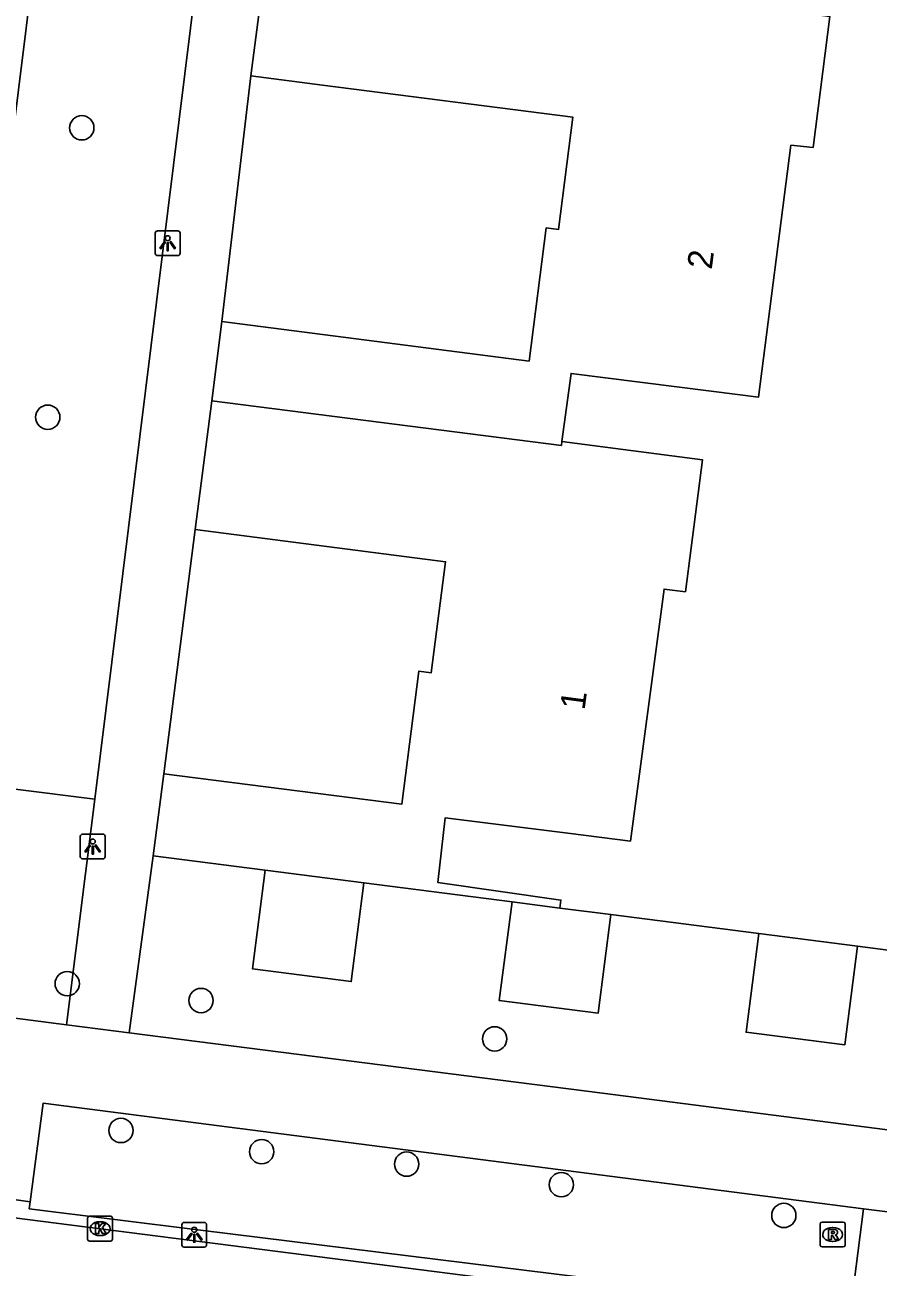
# Model space of a CAD drawing. Extents: x 162186 to 163152, y 385513 to 386513.
# Drawn here: x 162370.33 to 162404.64, y 386051 to 386100.97 of the extents above; entities that cross this region are included whole.
import ezdxf

# ---------------------------------------------------------------- set-up
doc = ezdxf.new("R2010")
doc.units = 0
for name, color, linetype in [('IMGEO_Boom', 7, 'Continuous'), ('IMGEO_Groenvoorziening', 7, 'Continuous'), ('IMGEO_Kolk', 7, 'Continuous'), ('IMGEO_Lichtpunt', 7, 'Continuous'), ('IMGEO_Muur', 7, 'Continuous'), ('IMGEO_Pand', 7, 'Continuous'), ('IMGEO_Pand_nummerreeks', 7, 'Continuous'), ('IMGEO_Rijbaan_lokaal_open', 7, 'Continuous'), ('IMGEO_Rioolput', 7, 'Continuous'), ('IMGEO_Voetpad_open', 7, 'Continuous')]:
    doc.layers.add(name, color=color, linetype=linetype)

msp = doc.modelspace()

# ---------------------------------------------------------------- linework, layer by layer
at = {"layer": 'IMGEO_Boom'}
for centre in [(162372.62, 386096.827), (162371.252, 386085.186), (162372.034, 386062.399), (162377.416, 386061.723), (162389.22, 386060.18), (162374.193, 386056.495), (162379.854, 386055.641), (162385.68, 386055.142), (162391.899, 386054.314), (162400.847, 386053.077)]:
    msp.add_circle(centre, 0.489, dxfattribs=at)
at = {"layer": 'IMGEO_Groenvoorziening'}
for points in [[(162373.204, 386123.496), (162366.618, 386070.643)], [(162366.618, 386070.643), (162373.139, 386069.824)], [(162383.966, 386066.454), (162383.456, 386062.487), (162379.488, 386062.996), (162379.998, 386066.964)], [(162393.886, 386065.179), (162393.376, 386061.212), (162389.408, 386061.722), (162389.918, 386065.69)], [(162391.837, 386065.443), (162393.886, 386065.179)], [(162393.886, 386065.179), (162399.838, 386064.413)], [(162403.805, 386063.903), (162403.294, 386059.936), (162399.328, 386060.446), (162399.838, 386064.413)], [(162399.838, 386064.413), (162403.805, 386063.903)], [(162403.805, 386063.903), (162406.781, 386063.52)]]:
    msp.add_lwpolyline(points, dxfattribs=at)
at = {"layer": 'IMGEO_Kolk'}
for p, q in [((162372.855, 386052.121), (162372.855, 386052.973)), ((162372.93, 386053.047), (162373.782, 386053.047)), ((162373.343, 386052.827), (162373.368, 386052.827)), ((162373.856, 386052.973), (162373.856, 386052.121)), ((162373.366, 386052.267), (162373.341, 386052.267)), ((162373.782, 386052.047), (162372.93, 386052.047))]:
    msp.add_line(p, q, dxfattribs=at)
for points in [[(162372.855, 386052.121), (162372.855, 386052.973)], [(162372.93, 386053.047), (162373.782, 386053.047)], [(162373.176, 386052.747), (162373.299, 386052.747), (162373.299, 386052.596), (162373.429, 386052.747), (162373.593, 386052.747), (162373.447, 386052.596), (162373.6, 386052.347), (162373.448, 386052.347), (162373.363, 386052.511), (162373.299, 386052.444), (162373.299, 386052.347), (162373.176, 386052.347), (162373.176, 386052.747)], [(162373.856, 386052.973), (162373.856, 386052.121)], [(162373.782, 386052.047), (162372.93, 386052.047)]]:
    msp.add_lwpolyline(points, dxfattribs=at)
for centre, start, end in [((162372.932, 386052.971), 91.552, 178.448), ((162372.932, 386052.971), 91.552, 178.448), ((162373.78, 386052.971), 1.552, 88.448), ((162373.78, 386052.971), 1.552, 88.448), ((162372.932, 386052.123), 181.552, 268.448), ((162372.932, 386052.123), 181.552, 268.448), ((162373.78, 386052.123), 271.552, 358.448), ((162373.78, 386052.123), 271.552, 358.448)]:
    msp.add_arc(centre, 0.0765, start, end, dxfattribs=at)
for centre, major_axis, ratio, start_param, end_param in [((162373.342, 386052.547), (-0.387, 0.002), 0.722429, 4.712389, 7.853982), ((162373.367, 386052.547), (-0.39, 0.002), 0.717154, 1.570796, 4.712389)]:
    msp.add_ellipse(centre, major_axis=major_axis, ratio=ratio, start_param=start_param, end_param=end_param, dxfattribs=at)
at = {"layer": 'IMGEO_Lichtpunt'}
for p, q in [((162375.575, 386092.586), (162375.575, 386091.779)), ((162375.575, 386092.586), (162375.575, 386091.779)), ((162376.477, 386092.681), (162375.669, 386092.681)), ((162376.477, 386092.681), (162375.669, 386092.681)), ((162376.571, 386091.779), (162376.571, 386092.586)), ((162376.571, 386091.779), (162376.571, 386092.586)), ((162375.669, 386091.685), (162376.477, 386091.685)), ((162375.669, 386091.685), (162376.477, 386091.685)), ((162372.561, 386068.322), (162372.561, 386067.515)), ((162372.561, 386068.322), (162372.561, 386067.515)), ((162373.463, 386068.417), (162372.655, 386068.417)), ((162373.463, 386068.417), (162372.655, 386068.417)), ((162373.557, 386067.515), (162373.557, 386068.322)), ((162373.557, 386067.515), (162373.557, 386068.322)), ((162372.655, 386067.421), (162373.463, 386067.421)), ((162372.655, 386067.421), (162373.463, 386067.421)), ((162376.643, 386052.705), (162376.643, 386051.898)), ((162376.643, 386052.705), (162376.643, 386051.898)), ((162377.545, 386052.8), (162376.737, 386052.8)), ((162377.545, 386052.8), (162376.737, 386052.8)), ((162377.639, 386051.898), (162377.639, 386052.705)), ((162377.639, 386051.898), (162377.639, 386052.705)), ((162376.737, 386051.804), (162377.545, 386051.804)), ((162376.737, 386051.804), (162377.545, 386051.804))]:
    msp.add_line(p, q, dxfattribs=at)
for points in [[(162375.949, 386092.25), (162375.988, 386092.222), (162375.8, 386091.96), (162375.762, 386091.987), (162375.949, 386092.25)], [(162376.051, 386092.202), (162376.098, 386092.202), (162376.098, 386091.88), (162376.051, 386091.88), (162376.051, 386092.202)], [(162376.161, 386092.222), (162376.199, 386092.249), (162376.386, 386091.987), (162376.347, 386091.959), (162376.161, 386092.222)], [(162372.935, 386067.986), (162372.974, 386067.958), (162372.786, 386067.696), (162372.748, 386067.723), (162372.935, 386067.986)], [(162373.037, 386067.938), (162373.084, 386067.938), (162373.084, 386067.616), (162373.037, 386067.616), (162373.037, 386067.938)], [(162373.147, 386067.958), (162373.185, 386067.985), (162373.372, 386067.723), (162373.333, 386067.695), (162373.147, 386067.958)], [(162377.017, 386052.369), (162377.056, 386052.341), (162376.868, 386052.079), (162376.83, 386052.106), (162377.017, 386052.369)], [(162377.119, 386052.321), (162377.166, 386052.321), (162377.166, 386051.999), (162377.119, 386051.999), (162377.119, 386052.321)], [(162377.229, 386052.341), (162377.267, 386052.368), (162377.454, 386052.106), (162377.415, 386052.078), (162377.229, 386052.341)]]:
    msp.add_lwpolyline(points, dxfattribs=at)
for centre in [(162376.074, 386092.384), (162373.06, 386068.12), (162377.142, 386052.503)]:
    msp.add_circle(centre, 0.0994, dxfattribs=at)
for centre, start, end in [((162375.669, 386092.586), 90, 180), ((162375.669, 386092.586), 90, 180), ((162376.477, 386092.586), 0, 90), ((162376.477, 386092.586), 0, 90), ((162375.669, 386091.779), 180, 270), ((162375.669, 386091.779), 180, 270), ((162376.477, 386091.779), 270, 0), ((162376.477, 386091.779), 270, 360), ((162372.655, 386068.322), 90, 180), ((162372.655, 386068.322), 90, 180), ((162373.463, 386068.322), 0, 90), ((162373.463, 386068.322), 0, 90), ((162372.655, 386067.515), 180, 270), ((162372.655, 386067.515), 180, 270), ((162373.463, 386067.515), 270, 0), ((162373.463, 386067.515), 270, 360), ((162376.737, 386052.705), 90, 180), ((162376.737, 386052.705), 90, 180), ((162377.545, 386052.705), 0, 90), ((162377.545, 386052.705), 0, 90), ((162376.737, 386051.898), 180, 270), ((162376.737, 386051.898), 180, 270), ((162377.545, 386051.898), 270, 0), ((162377.545, 386051.898), 270, 360)]:
    msp.add_arc(centre, 0.0946, start, end, dxfattribs=at)
at = {"layer": 'IMGEO_Muur'}
msp.add_lwpolyline([(162377.179, 386080.668), (162375.915, 386070.846)], dxfattribs=at)
at = {"layer": 'IMGEO_Pand'}
for points in [[(162379.417, 386098.915), (162380.067, 386103.971)], [(162391.923, 386084.208), (162392.295, 386086.949), (162397.931, 386086.235), (162399.834, 386085.994), (162401.129, 386096.126), (162402.02, 386096.032), (162402.695, 386101.305), (162398.034, 386101.902)], [(162378.254, 386089.03), (162390.603, 386087.444), (162391.292, 386092.8), (162391.788, 386092.737), (162392.368, 386097.25), (162382.301, 386098.544), (162379.417, 386098.915)], [(162377.844, 386085.841), (162378.254, 386089.03)], [(162377.179, 386080.668), (162377.844, 386085.841)], [(162377.844, 386085.841), (162391.901, 386084.049), (162391.923, 386084.208)], [(162391.923, 386084.208), (162397.575, 386083.478), (162396.89, 386078.164), (162396.031, 386078.274), (162394.676, 386068.137), (162392.269, 386068.44), (162387.235, 386069.074), (162386.935, 386066.474), (162391.883, 386065.76), (162391.837, 386065.443)], [(162377.179, 386080.668), (162387.246, 386079.374), (162386.672, 386074.91), (162386.176, 386074.973), (162385.487, 386069.617), (162375.915, 386070.846)], [(162375.49, 386067.543), (162375.915, 386070.846)], [(162375.49, 386067.543), (162379.998, 386066.964)], [(162379.998, 386066.964), (162383.966, 386066.454)], [(162383.966, 386066.454), (162389.918, 386065.69)], [(162389.918, 386065.69), (162391.837, 386065.443)]]:
    msp.add_lwpolyline(points, dxfattribs=at)
at = {"layer": 'IMGEO_Rijbaan_lokaal_open'}
for points in [[(162331.957, 386057.856), (162333.146, 386057.71), (162370.437, 386052.921), (162392.654, 386050.067), (162403.455, 386048.678)], [(162403.53, 386049.259), (162404.055, 386053.339)], [(162404.055, 386053.339), (162410.404, 386052.546), (162417.099, 386051.668)]]:
    msp.add_lwpolyline(points, dxfattribs=at)
at = {"layer": 'IMGEO_Rioolput'}
for p, q in [((162402.309, 386051.885), (162402.309, 386052.737)), ((162402.384, 386052.811), (162403.236, 386052.811)), ((162402.797, 386052.591), (162402.822, 386052.591)), ((162403.31, 386052.737), (162403.31, 386051.885)), ((162403.236, 386051.811), (162402.384, 386051.811)), ((162402.82, 386052.031), (162402.795, 386052.031))]:
    msp.add_line(p, q, dxfattribs=at)
for points in [[(162402.309, 386051.885), (162402.309, 386052.737)], [(162402.384, 386052.811), (162403.236, 386052.811)], [(162403.31, 386052.737), (162403.31, 386051.885)], [(162402.898, 386052.509), (162402.646, 386052.511), (162402.646, 386052.111)], [(162402.646, 386052.111), (162402.77, 386052.111), (162402.77, 386052.273), (162402.781, 386052.273)], [(162402.824, 386052.43), (162402.77, 386052.43), (162402.77, 386052.349)], [(162402.77, 386052.349), (162402.822, 386052.349)], [(162402.828, 386052.244), (162402.899, 386052.111), (162403.039, 386052.111), (162402.974, 386052.237)], [(162403.236, 386051.811), (162402.384, 386051.811)]]:
    msp.add_lwpolyline(points, dxfattribs=at)
for centre, radius, start, end in [((162402.386, 386052.735), 0.0765, 91.552, 178.448), ((162402.386, 386052.735), 0.0765, 91.552, 178.448), ((162403.234, 386052.735), 0.0765, 1.552, 88.448), ((162403.234, 386052.735), 0.0765, 1.552, 88.448), ((162402.78, 386052.22), 0.0533, 26.0293, 88.6989), ((162402.806, 386052.538), 0.19, 274.7715, 282.9687), ((162402.83, 386052.334), 0.0964, 77.0061, 93.1865), ((162402.844, 386052.391), 0.0378, 276.6634, 79.6772), ((162402.897, 386052.399), 0.109, 350.3612, 89.416), ((162402.895, 386052.399), 0.112, 277.5842, 350.9817), ((162402.879, 386052.184), 0.108, 29.5134, 73.7905), ((162402.386, 386051.887), 0.0765, 181.552, 268.448), ((162402.386, 386051.887), 0.0765, 181.552, 268.448), ((162403.234, 386051.887), 0.0765, 271.552, 358.448), ((162403.234, 386051.887), 0.0765, 271.552, 358.448)]:
    msp.add_arc(centre, radius, start, end, dxfattribs=at)
for centre, major_axis, ratio, start_param, end_param in [((162402.796, 386052.311), (-0.387, 0.002), 0.722429, 4.712389, 7.853982), ((162402.821, 386052.311), (-0.39, 0.002), 0.717154, 1.570796, 4.712389)]:
    msp.add_ellipse(centre, major_axis=major_axis, ratio=ratio, start_param=start_param, end_param=end_param, dxfattribs=at)
at = {"layer": 'IMGEO_Voetpad_open'}
for points in [[(162379.704, 386122.675), (162373.139, 386069.824)], [(162378.254, 386089.03), (162379.417, 386098.915)], [(162375.915, 386070.846), (162377.179, 386080.668)], [(162373.139, 386069.824), (162372.011, 386060.742)], [(162374.53, 386060.423), (162375.49, 386067.543)], [(162372.011, 386060.742), (162354.832, 386062.964)], [(162372.011, 386060.742), (162374.53, 386060.423)], [(162405.95, 386056.404), (162393.558, 386057.997), (162374.53, 386060.423)], [(162404.055, 386053.339), (162371.062, 386057.59), (162370.542, 386053.63)], [(162368.193, 386053.958), (162370.542, 386053.63)], [(162370.542, 386053.63), (162370.505, 386053.346), (162377.399, 386052.492), (162403.53, 386049.259)]]:
    msp.add_lwpolyline(points, dxfattribs=at)

# ---------------------------------------------------------------- texts
at = {"layer": 'IMGEO_Pand_nummerreeks'}
for s, rotation, p in [('2', 82.7179, (162397.947, 386091.105)), ('1', 82.3865, (162392.834, 386073.38))]:
    msp.add_text(s, height=1, rotation=rotation, dxfattribs=at).set_placement(p)

doc.saveas('drawing.dxf')
